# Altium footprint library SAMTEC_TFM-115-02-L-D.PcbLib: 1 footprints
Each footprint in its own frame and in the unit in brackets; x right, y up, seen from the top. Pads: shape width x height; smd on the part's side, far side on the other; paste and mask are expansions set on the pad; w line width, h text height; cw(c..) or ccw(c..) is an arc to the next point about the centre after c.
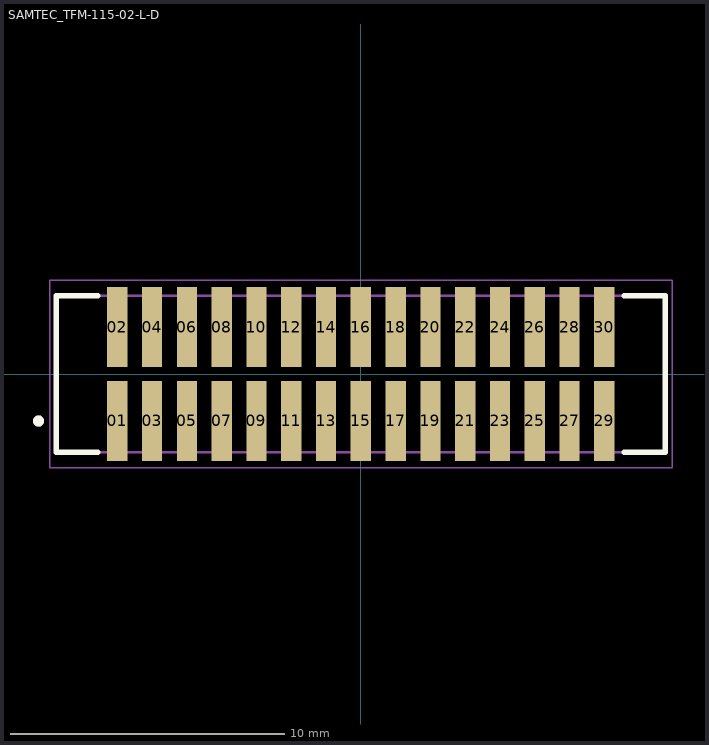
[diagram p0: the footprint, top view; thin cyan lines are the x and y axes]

## SAMTEC_TFM-115-02-L-D [mm]
pads (30):
  rect 0.74x2.92 smd: 01(-8.89,-1.715) 02(-8.89,1.715) 03(-7.62,-1.715) 04(-7.62,1.715) 05(-6.35,-1.715) 06(-6.35,1.715) 07(-5.08,-1.715) 08(-5.08,1.715) 09(-3.81,-1.715) 10(-3.81,1.715) 11(-2.54,-1.715) 12(-2.54,1.715) 13(-1.27,-1.715) 14(-1.27,1.715) 15(0,-1.715) 16(0,1.715) 17(1.27,-1.715) 18(1.27,1.715) 19(2.54,-1.715) 20(2.54,1.715) 21(3.81,-1.715) 22(3.81,1.715) 23(5.08,-1.715) 24(5.08,1.715) 25(6.35,-1.715) 26(6.35,1.715) 27(7.62,-1.715) 28(7.62,1.715) 29(8.89,-1.715) 30(8.89,1.715)
Top Overlay:
  circle w0.2: c-11.765,-1.715 r0.1
  lines w0.2: -9.61,-2.86 -11.115,-2.86 -11.115,2.86 -9.61,2.86 ; 9.61,-2.86 11.115,-2.86 11.115,2.86 9.61,2.86
Mechanical 13:
  circle w0.2: c-11.765,-1.715 r0.1
  lines w0.1: -11.115,-2.86 -11.115,2.86 ; -11.115,-2.86 11.115,-2.86 ; -11.115,-2.86 -11.115,2.86 ; -11.115,2.86 11.115,2.86 ; -11.115,2.86 11.115,2.86 ; 11.115,-2.86 11.115,2.86 ; 11.115,-2.86 11.115,2.86
Mechanical 15:
  lines w0.05: -11.365,-3.425 11.365,-3.425 11.365,3.425 -11.365,3.425 -11.365,-3.425
3D body "TFM-115-02-L-D.stp": height 5.71, standoff -0.03, extent -11.112,-3.048 11.112,2.921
